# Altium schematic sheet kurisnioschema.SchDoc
size A4 portrait
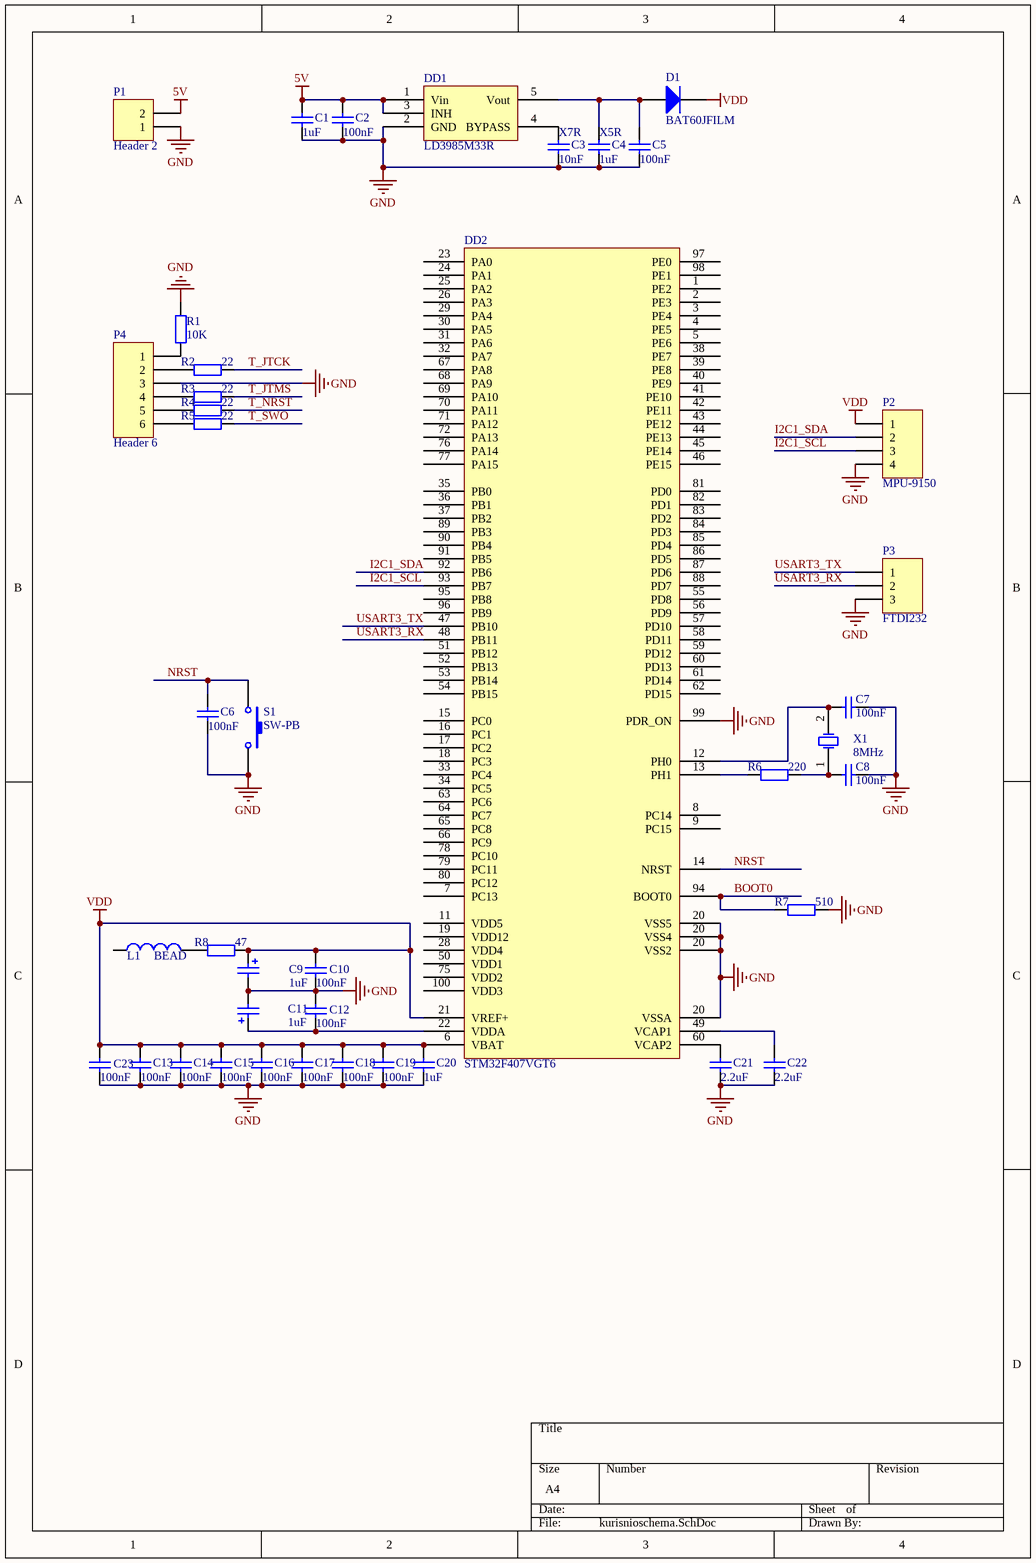
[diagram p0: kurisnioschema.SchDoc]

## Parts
C1  value 1uF  [RAD-0.3]  (hidden comment: Cap)
C2  value 100nF  [RAD-0.3]  (hidden comment: Cap)
C3  X7R  value 10nF  [RAD-0.3]
C4  X5R  value 1uF  [RAD-0.3]
C5  value 100nF  [RAD-0.3]  (hidden comment: Cap)
C6  value 100nF  [RAD-0.3]  (hidden comment: Cap)
C7  value 100nF  [RAD-0.3]  (hidden comment: Cap)
C8  value 100nF  [RAD-0.3]  (hidden comment: Cap)
C9  value 1uF  [POLAR0.8]  (hidden comment: Cap Pol2)
C10  value 100nF  [RAD-0.3]  (hidden comment: Cap)
C11  value 1uF  [POLAR0.8]  (hidden comment: Cap Pol2)
C12  value 100nF  [RAD-0.3]  (hidden comment: Cap)
C13  value 100nF  [RAD-0.3]  (hidden comment: Cap)
C14  value 100nF  [RAD-0.3]  (hidden comment: Cap)
C15  value 100nF  [RAD-0.3]  (hidden comment: Cap)
C16  value 100nF  [RAD-0.3]  (hidden comment: Cap)
C17  value 100nF  [RAD-0.3]  (hidden comment: Cap)
C18  value 100nF  [RAD-0.3]  (hidden comment: Cap)
C19  value 100nF  [RAD-0.3]  (hidden comment: Cap)
C20  value 1uF  [RAD-0.3]  (hidden comment: Cap)
C21  value 2.2uF  [RAD-0.3]  (hidden comment: Cap)
C22  value 2.2uF  [RAD-0.3]  (hidden comment: Cap)
C23  value 100nF  [RAD-0.3]  (hidden comment: Cap)
D1  BAT60JFILM  [SMC]
DD1  LD3985M33R
DD2  STM32F407VGT6
L1  BEAD  [0402-A]
P1  Header 2  [HDR1X2]
P2  MPU-9150  [HDR1X4]
P3  FTDI232  [HDR1X3]
P4  Header 6  [HDR1X6]
R1  value 10K  [AXIAL-0.4]  (hidden comment: Res2)
R2  value 22  [AXIAL-0.4]  (hidden comment: Res2)
R3  value 22  [AXIAL-0.4]  (hidden comment: Res2)
R4  value 22  [AXIAL-0.4]  (hidden comment: Res2)
R5  value 22  [AXIAL-0.4]  (hidden comment: Res2)
R6  value 220  [AXIAL-0.4]  (hidden comment: Res2)
R7  value 510  [AXIAL-0.4]  (hidden comment: Res2)
R8  value 47  [AXIAL-0.4]  (hidden comment: Res2)
S1  SW-PB  [SPST-2]
X1  8MHz  [R38]

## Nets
5V: C1.2 C2.2 DD1.1(Vin) DD1.3(INH) P1.2
GND: C1.1 C2.1 C3.1 C4.1 C5.1 C6.1 C7.1 C8.1 C9.2 C10.1 C11.2 C12.2 C13.1 C14.1 C15.1 C16.1 C17.1 C18.1 C19.1 C20.1 C21.1 C22.1 C23.1 DD1.2(GND) DD2.20(VSSA) DD2.99(PDR_ON) P1.1 P2.4 P3.3 P4.3 R1.1 R7.1 S1.2
VDD: C9.1 C10.2 C13.2 C14.2 C15.2 C16.2 C17.2 C18.2 C19.2 C20.2 C23.2 D1.2(K) DD2.6(VBAT) DD2.21(VREF+) P2.1 R8.1
BOOT0: DD2.94(BOOT0) R7.2
I2C1_SCL: DD2.93(PB7) P2.3
I2C1_SDA: DD2.92(PB6) P2.2
NRST: C6.2 DD2.14(NRST) S1.1
T_JTCK: R2.1
T_JTMS: R3.1
T_NRST: R4.1
T_SWO: R5.1
USART3_RX: DD2.48(PB11) P3.2
USART3_TX: DD2.47(PB10) P3.1
NetC3_2: C3.2 DD1.4(BYPASS)
NetC4_2: C4.2 C5.2 D1.1(A) DD1.5(Vout)
NetC7_2: C7.2 DD2.12(PH0) X1.2(OSC2)
NetC8_2: C8.2 R6.1 X1.1(OSC1)
NetC11_1: C11.1 C12.1 DD2.22(VDDA)
NetC21_2: C21.2 DD2.60(PD13)
NetC22_2: C22.2 DD2.49(VCAP1)
NetDD2_13: DD2.13(PH1) R6.2
NetL1_2: L1.2 R8.2
NetP4_1: P4.1 R1.2
NetP4_2: P4.2 R2.2
NetP4_4: P4.4 R3.2
NetP4_5: P4.5 R4.2
NetP4_6: P4.6 R5.2

Not connected (* = marked no-connect by the designer): DD2 1(PE2) 2(PE3) 3(PE4) 4(PE5) 5(PE6) 7(PC13) 8(PC14) 9(PC15) 11(VDD5) 15(PC0) 16(PC1) 17(PC2) 18(PC3) 19(VDD12) 23(PA0) 24(PA1) 25(PA2) 26(PA3) 28(VDD4) 29(PA4) 30(PA5) 31(PA6) 32(PA7) 33(PC4) 34(PC5) 35(PB0) 36(PB1) 37(PB2) 38(PE7) 39(PE8) 40(PE9) 41(PE10) 42(PE11) 43(PE12) 44(PE13) 45(PE14) 46(PE15) 50(VDD1) 51(PB12) 52(PB13) 53(PB14) 54(PB15) 55(PD8) 56(PD9) 57(PD10) 58(PD11) 59(PD12) 61(PD14) 62(PD15) 63(PC6) 64(PC7) 65(PC8) 66(PC9) 67(PA8) 68(PA9) 69(PA10) 70(PA11) 71(PA12) 72(PA13) 75(VDD2) 76(PA14) 77(PA15) 78(PC10) 79(PC11) 80(PC12) 81(PD0) 82(PD1) 83(PD2) 84(PD3) 85(PD4) 86(PD5) 87(PD6) 88(PD7) 89(PB3) 90(PB4) 91(PB5) 95(PB8) 96(PB9) 97(PE0) 98(PE1) 100(VDD3); L1 1

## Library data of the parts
C1-C8 C10 C12-C23 = Cap: Capacitor
C9 C11 = Cap Pol2: Polarized Capacitor (Axial)
D1 = Diode: Default Diode
DD2 = STM32F407VGT6: STM32F407VGT6 ARM-Cortex-M4F microcontroller
L1 = Inductor: Code_IEC: 1005; Value: 10mH
P1 = Header 2: Header, 2-Pin
P2 = Header 4: Header, 4-Pin
P3 = Header 3: Header, 3-Pin
P4 = Header 6: Header, 6-Pin
R1-R8 = Res2: Resistor
S1 = SW-PB: Switch
X1 = XTAL: Crystal Oscillator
